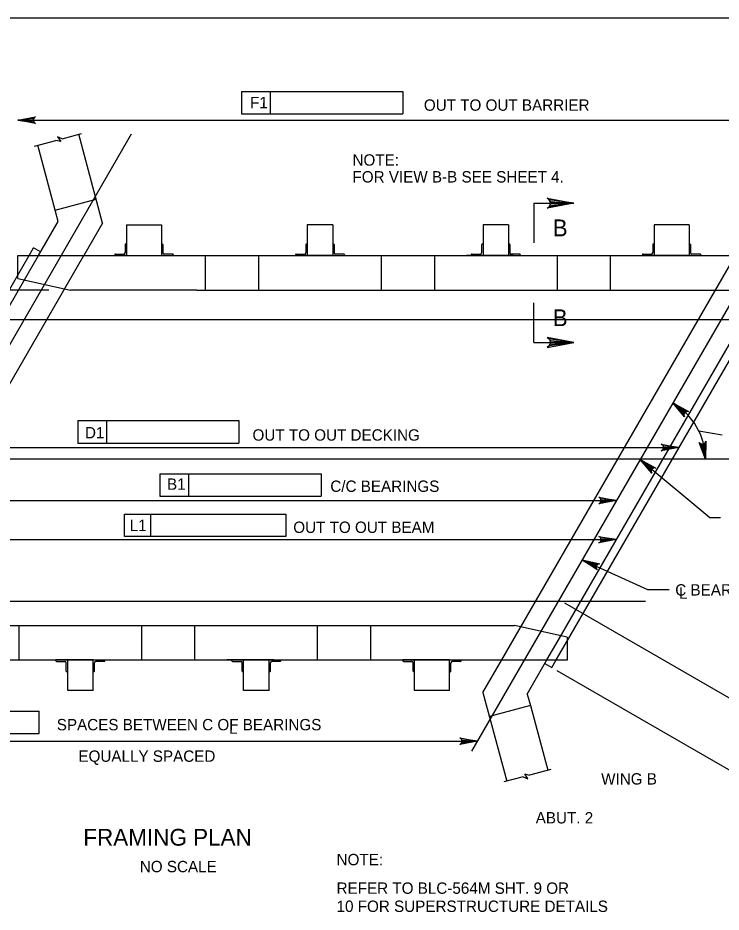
# Model space of a CAD drawing. Extents: x 638175 to 640495, y 294277 to 298435.
# Drawn here: x 638659.6 to 638845, y 295214.5 to 295450.5 of the extents above; entities that cross this region are included whole.
import ezdxf

# ---------------------------------------------------------------- set-up
doc = ezdxf.new("R2010")
doc.units = 0
for name, color, linetype in [('2', 7, 'Continuous'), ('3', 7, 'Continuous'), ('4', 7, 'Continuous')]:
    doc.layers.add(name, color=color, linetype=linetype)

msp = doc.modelspace()

# ---------------------------------------------------------------- linework, layer by layer
at = {"layer": '2'}
for p, q in [((638475.46, 295450.46), (639261.46, 295450.46)), ((638681.87, 295396.3), (638675.59, 295419.73)), ((638669.38, 295399.76), (638664.8, 295416.84)), ((638669.38, 295399.76), (638680.17, 295402.65)), ((638670.19, 295396.73), (638669.38, 295399.76)), ((638795.64, 295401.55), (638795.64, 295391.07)), ((638795.64, 295401.55), (638806.12, 295401.55)), ((638665, 295387.76), (638670.19, 295396.73)), ((638681.87, 295396.3), (638676.94, 295387.76)), ((638688.19, 295395.84), (638697.43, 295395.84)), ((638688.19, 295395.84), (638688.19, 295387.75)), ((638697.43, 295395.84), (638697.43, 295387.75)), ((638742.58, 295395.84), (638735.85, 295395.84)), ((638742.58, 295395.84), (638735.85, 295395.84)), ((638735.85, 295395.84), (638735.85, 295387.75)), ((638742.58, 295395.84), (638742.58, 295387.75)), ((638788.95, 295395.84), (638782.22, 295395.84)), ((638788.95, 295395.84), (638782.22, 295395.84)), ((638788.95, 295395.84), (638782.22, 295395.84)), ((638782.22, 295395.84), (638782.22, 295387.75)), ((638788.95, 295395.84), (638788.95, 295387.75)), ((638836.56, 295395.84), (638827.33, 295395.84)), ((638827.33, 295395.84), (638827.33, 295387.75)), ((638836.56, 295395.84), (638836.56, 295387.75)), ((638687.83, 295390.66), (638687.83, 295388.48)), ((638688.01, 295390.84), (638688.19, 295390.84)), ((638688.19, 295390.84), (638688.19, 295387.75)), ((638697.61, 295390.84), (638697.43, 295390.84)), ((638697.43, 295390.84), (638697.43, 295387.75)), ((638697.79, 295390.66), (638697.79, 295388.48)), ((638735.49, 295390.66), (638735.49, 295388.48)), ((638735.67, 295390.84), (638735.85, 295390.84)), ((638735.85, 295390.84), (638735.85, 295387.75)), ((638742.76, 295390.84), (638742.58, 295390.84)), ((638742.58, 295390.84), (638742.58, 295387.75)), ((638742.95, 295390.66), (638742.95, 295388.48)), ((638781.85, 295390.66), (638781.85, 295388.48)), ((638782.04, 295390.84), (638782.22, 295390.84)), ((638782.22, 295390.84), (638782.22, 295387.75)), ((638789.13, 295390.84), (638788.95, 295390.84)), ((638788.95, 295390.84), (638788.95, 295387.75)), ((638789.31, 295390.66), (638789.31, 295388.48)), ((638826.96, 295390.66), (638826.96, 295388.48)), ((638827.15, 295390.84), (638827.33, 295390.84)), ((638827.33, 295390.84), (638827.33, 295387.75)), ((638836.75, 295390.84), (638836.56, 295390.84)), ((638836.56, 295390.84), (638836.56, 295387.75)), ((638836.93, 295390.66), (638836.93, 295388.48)), ((638615.32, 295281.03), (638676.94, 295387.76)), ((638659.57, 295387.75), (638863.14, 295387.75)), ((638659.57, 295382.59), (638662.55, 295387.75)), ((638659.57, 295381.72), (638659.57, 295387.75)), ((638662.02, 295382.59), (638665, 295387.76)), ((638662.55, 295387.75), (638663.71, 295389.77)), ((638665.56, 295388.71), (638663.71, 295389.77)), ((638665, 295387.76), (638860.69, 295387.76)), ((638685.1, 295387.94), (638685.1, 295387.75)), ((638688.19, 295387.75), (638685.1, 295387.75)), ((638685.28, 295388.12), (638687.46, 295388.12)), ((638688.19, 295387.75), (638697.43, 295387.75)), ((638697.43, 295387.75), (638700.52, 295387.75)), ((638700.34, 295388.12), (638698.15, 295388.12)), ((638700.52, 295387.94), (638700.52, 295387.75)), ((638708.98, 295387.75), (638708.98, 295378.63)), ((638723.05, 295387.75), (638723.05, 295378.63)), ((638732.76, 295387.94), (638732.76, 295387.75)), ((638735.85, 295387.75), (638732.76, 295387.75)), ((638732.95, 295388.12), (638735.13, 295388.12)), ((638742.58, 295387.75), (638735.85, 295387.75)), ((638742.58, 295387.75), (638735.85, 295387.75)), ((638742.58, 295387.75), (638745.67, 295387.75)), ((638745.49, 295388.12), (638743.31, 295388.12)), ((638745.67, 295387.94), (638745.67, 295387.75)), ((638755.39, 295387.75), (638755.39, 295378.63)), ((638769.41, 295387.75), (638769.41, 295378.63)), ((638780.96, 295387.75), (638777.87, 295387.75)), ((638779.13, 295387.94), (638779.13, 295387.75)), ((638782.22, 295387.75), (638779.13, 295387.75)), ((638779.31, 295388.12), (638781.49, 295388.12)), ((638790.2, 295387.75), (638780.96, 295387.75)), ((638788.95, 295387.75), (638782.22, 295387.75)), ((638788.95, 295387.75), (638782.22, 295387.75)), ((638787.14, 295281.03), (638848.76, 295387.76)), ((638788.95, 295387.75), (638792.04, 295387.75)), ((638791.85, 295388.12), (638789.67, 295388.12)), ((638790.2, 295387.75), (638793.29, 295387.75)), ((638792.04, 295387.94), (638792.04, 295387.75)), ((638801.75, 295387.75), (638801.75, 295378.63)), ((638815.78, 295387.75), (638815.78, 295378.63)), ((638824.24, 295387.94), (638824.24, 295387.75)), ((638827.33, 295387.75), (638824.24, 295387.75)), ((638824.42, 295388.12), (638826.6, 295388.12)), ((638836.56, 295387.75), (638827.33, 295387.75)), ((638836.56, 295387.75), (638839.65, 295387.75)), ((638839.47, 295388.12), (638837.29, 295388.12)), ((638839.65, 295387.94), (638839.65, 295387.75)), ((638604.93, 295287.95), (638659.57, 295382.59)), ((638606.97, 295287.25), (638662.02, 295382.59)), ((638659.57, 295381.72), (638673.41, 295378.63)), ((638802.05, 295286.2), (638857.1, 295381.54)), ((638804.51, 295286.2), (638859.56, 295381.54)), ((638706.72, 295378.63), (638673.41, 295378.63)), ((638706.72, 295378.63), (638849.29, 295378.63)), ((638795.64, 295364.82), (638795.64, 295375.31)), ((638795.64, 295364.82), (638806.12, 295364.82)), ((638648.08, 295290.15), (638790.52, 295290.15)), ((638659.88, 295281.03), (638659.88, 295290.15)), ((638692.22, 295281.03), (638692.22, 295290.15)), ((638706.24, 295281.03), (638706.24, 295290.15)), ((638738.58, 295281.03), (638738.58, 295290.15)), ((638752.61, 295281.03), (638752.61, 295290.15)), ((638804.39, 295287.05), (638790.52, 295290.15)), ((638799.07, 295281.03), (638802.05, 295286.2)), ((638801.53, 295281.03), (638804.51, 295286.2)), ((638804.39, 295287.05), (638804.39, 295281.03)), ((638600.93, 295281.03), (638804.51, 295281.03)), ((638600.93, 295281.03), (638799.6, 295281.03)), ((638603.38, 295281.03), (638802.05, 295281.03)), ((638669.59, 295280.84), (638669.59, 295281.03)), ((638672.69, 295281.03), (638669.59, 295281.03)), ((638669.78, 295280.66), (638671.96, 295280.66)), ((638672.32, 295278.12), (638672.32, 295280.3)), ((638679.41, 295281.03), (638672.69, 295281.03)), ((638679.41, 295281.03), (638672.69, 295281.03)), ((638672.69, 295277.94), (638672.69, 295281.03)), ((638672.69, 295272.94), (638672.69, 295281.03)), ((638679.41, 295281.03), (638682.5, 295281.03)), ((638679.41, 295277.94), (638679.41, 295281.03)), ((638679.41, 295272.94), (638679.41, 295281.03)), ((638679.78, 295278.12), (638679.78, 295280.3)), ((638682.32, 295280.66), (638680.14, 295280.66)), ((638682.5, 295280.84), (638682.5, 295281.03)), ((638717.79, 295281.03), (638714.7, 295281.03)), ((638715.96, 295280.84), (638715.96, 295281.03)), ((638719.05, 295281.03), (638715.96, 295281.03)), ((638716.14, 295280.66), (638718.32, 295280.66)), ((638727.03, 295281.03), (638717.79, 295281.03)), ((638718.69, 295278.12), (638718.69, 295280.3)), ((638725.78, 295281.03), (638719.05, 295281.03)), ((638725.78, 295281.03), (638719.05, 295281.03)), ((638719.05, 295277.94), (638719.05, 295281.03)), ((638719.05, 295272.94), (638719.05, 295281.03)), ((638725.78, 295281.03), (638728.87, 295281.03)), ((638725.78, 295277.94), (638725.78, 295281.03)), ((638725.78, 295272.94), (638725.78, 295281.03)), ((638726.14, 295278.12), (638726.14, 295280.3)), ((638728.69, 295280.66), (638726.5, 295280.66)), ((638727.03, 295281.03), (638730.12, 295281.03)), ((638728.87, 295280.84), (638728.87, 295281.03)), ((638761.07, 295280.84), (638761.07, 295281.03)), ((638764.16, 295281.03), (638761.07, 295281.03)), ((638761.25, 295280.66), (638763.43, 295280.66)), ((638763.79, 295278.12), (638763.79, 295280.3)), ((638773.39, 295281.03), (638764.16, 295281.03)), ((638764.16, 295272.94), (638764.16, 295281.03)), ((638764.16, 295277.94), (638764.16, 295281.03)), ((638773.39, 295281.03), (638776.49, 295281.03)), ((638773.39, 295272.94), (638773.39, 295281.03)), ((638773.39, 295277.94), (638773.39, 295281.03)), ((638773.76, 295278.12), (638773.76, 295280.3)), ((638776.3, 295280.66), (638774.12, 295280.66)), ((638776.49, 295280.84), (638776.49, 295281.03)), ((638782.2, 295272.48), (638787.14, 295281.03)), ((638793.89, 295272.05), (638799.07, 295281.03)), ((638798.52, 295280.07), (638800.36, 295279.01)), ((638800.36, 295279.01), (638801.53, 295281.03)), ((638672.5, 295277.94), (638672.69, 295277.94)), ((638679.59, 295277.94), (638679.41, 295277.94)), ((638718.87, 295277.94), (638719.05, 295277.94)), ((638725.96, 295277.94), (638725.78, 295277.94)), ((638763.98, 295277.94), (638764.16, 295277.94)), ((638773.58, 295277.94), (638773.39, 295277.94)), ((638679.41, 295272.94), (638672.69, 295272.94)), ((638679.41, 295272.94), (638672.69, 295272.94)), ((638725.78, 295272.94), (638719.05, 295272.94)), ((638725.78, 295272.94), (638719.05, 295272.94)), ((638725.78, 295272.94), (638719.05, 295272.94)), ((638773.39, 295272.94), (638764.16, 295272.94)), ((638782.2, 295272.48), (638788.48, 295249.06)), ((638793.89, 295272.05), (638794.7, 295269.03)), ((638638.68, 295267.51), (638665.18, 295267.51)), ((638665.18, 295261.6), (638665.18, 295267.51)), ((638794.7, 295269.03), (638783.91, 295266.13)), ((638794.7, 295269.03), (638799.27, 295251.95)), ((638638.67, 295261.6), (638665.18, 295261.6))]:
    msp.add_line(p, q, dxfattribs=at)
for points in [[(638806.12, 295401.55), (638799.13, 295400.24), (638799.67, 295400.62), (638799.95, 295401.08), (638800.03, 295401.55), (638799.95, 295402.02), (638799.67, 295402.49), (638799.13, 295402.86), (638806.12, 295401.55), (638799.67, 295402.49), (638799.95, 295402.02), (638806.12, 295401.55), (638800.03, 295401.55), (638799.95, 295401.08), (638806.12, 295401.55), (638799.67, 295400.62)], [(638806.12, 295364.82), (638799.13, 295366.13), (638799.67, 295365.76), (638799.95, 295365.29), (638800.03, 295364.82), (638799.95, 295364.35), (638799.67, 295363.89), (638799.13, 295363.51), (638806.12, 295364.82), (638799.67, 295363.89), (638799.95, 295364.35), (638806.12, 295364.82), (638800.03, 295364.82), (638799.95, 295365.29), (638806.12, 295364.82), (638799.67, 295365.76)]]:
    msp.add_lwpolyline(points, dxfattribs=at)
for centre, radius, start, end in [((638688.01, 295390.66), 0.182, 90, 179.9984), ((638697.61, 295390.66), 0.182, 0.0016, 90), ((638735.67, 295390.66), 0.182, 90, 179.9984), ((638742.76, 295390.66), 0.182, 0.0016, 90), ((638782.04, 295390.66), 0.182, 90, 179.9984), ((638789.13, 295390.66), 0.182, 0.0016, 90), ((638827.15, 295390.66), 0.182, 90, 179.9984), ((638836.75, 295390.66), 0.182, 0.0016, 90), ((638685.28, 295387.94), 0.182, 90, 179.9984), ((638687.46, 295388.48), 0.364, 270, 359.9984), ((638698.15, 295388.48), 0.364, 180.0016, 270), ((638700.34, 295387.94), 0.182, 0.0016, 90), ((638732.95, 295387.94), 0.182, 90, 179.9984), ((638735.13, 295388.48), 0.364, 270, 359.9984), ((638743.31, 295388.48), 0.364, 180.0016, 270), ((638745.49, 295387.94), 0.182, 0.0016, 90), ((638779.31, 295387.94), 0.182, 90, 179.9984), ((638781.49, 295388.48), 0.364, 270, 359.9984), ((638789.67, 295388.48), 0.364, 180.0016, 270), ((638791.85, 295387.94), 0.182, 0.0016, 90), ((638824.42, 295387.94), 0.182, 90, 179.9984), ((638826.6, 295388.48), 0.364, 270, 359.9984), ((638837.29, 295388.48), 0.364, 180.0016, 270), ((638839.47, 295387.94), 0.182, 0.0016, 90), ((638669.78, 295280.84), 0.182, 180.0016, 270), ((638671.96, 295280.3), 0.364, 0.0016, 90), ((638680.14, 295280.3), 0.364, 90, 179.9984), ((638682.32, 295280.84), 0.182, 270, 359.9984), ((638716.14, 295280.84), 0.182, 180.0016, 270), ((638718.32, 295280.3), 0.364, 0.0016, 90), ((638726.5, 295280.3), 0.364, 90, 179.9984), ((638728.69, 295280.84), 0.182, 270, 359.9984), ((638761.25, 295280.84), 0.182, 180.0016, 270), ((638763.43, 295280.3), 0.364, 0.0016, 90), ((638774.12, 295280.3), 0.364, 90, 179.9984), ((638776.3, 295280.84), 0.182, 270, 359.9984), ((638672.5, 295278.12), 0.182, 180.0016, 270), ((638679.59, 295278.12), 0.182, 270, 359.9984), ((638718.87, 295278.12), 0.182, 180.0016, 270), ((638725.96, 295278.12), 0.182, 270, 359.9984), ((638763.98, 295278.12), 0.182, 180.0016, 270), ((638773.58, 295278.12), 0.182, 270, 359.9984)]:
    msp.add_arc(centre, radius, start, end, dxfattribs=at)
at = {"layer": '3'}
for p, q in [((638671.23, 295418.56), (638670.03, 295419.08)), ((638670.03, 295419.08), (638670.85, 295417.83)), ((638671.23, 295418.56), (638676.36, 295419.93)), ((638663.96, 295416.61), (638669.56, 295418.11)), ((638670.85, 295417.83), (638669.56, 295418.11)), ((638793.22, 295250.96), (638794.51, 295250.67)), ((638794.05, 295249.71), (638793.22, 295250.96)), ((638800.11, 295252.17), (638794.51, 295250.67)), ((638792.84, 295250.22), (638787.72, 295248.85)), ((638792.84, 295250.22), (638794.05, 295249.71))]:
    msp.add_line(p, q, dxfattribs=at)
at = {"layer": '4'}
for p, q in [((638718.57, 295431.06), (638761.09, 295431.06)), ((638718.57, 295431.06), (638718.57, 295425.15)), ((638726.13, 295431.06), (638726.13, 295425.15)), ((638761.09, 295431.06), (638761.09, 295425.15)), ((638659.57, 295423.47), (638863.14, 295423.47)), ((638718.57, 295425.15), (638761.09, 295425.15)), ((638689.46, 295419.78), (638595.44, 295256.93)), ((638873.21, 295419.78), (638779.19, 295256.93)), ((638667.7, 295378.63), (638501.09, 295378.63)), ((638863.78, 295370.8), (638515.73, 295370.8)), ((638675.34, 295344.19), (638717.86, 295344.19)), ((638675.34, 295344.19), (638675.34, 295338.28)), ((638682.9, 295344.19), (638682.9, 295338.28)), ((638717.86, 295344.19), (638717.86, 295338.28)), ((638839.13, 295341.47), (638845.27, 295340.44)), ((638675.34, 295338.28), (638717.86, 295338.28)), ((638633.3, 295337.09), (638833.89, 295337.09)), ((638882.76, 295333.98), (638590.47, 295333.98)), ((638823.67, 295333.97), (638842.03, 295318.63)), ((638696.99, 295330.16), (638739.51, 295330.16)), ((638696.99, 295330.16), (638696.99, 295324.26)), ((638704.55, 295330.16), (638704.55, 295324.26)), ((638739.51, 295330.16), (638739.51, 295324.26)), ((638696.99, 295324.26), (638739.51, 295324.26)), ((638633.64, 295323.11), (638817.4, 295323.11)), ((638687.7, 295319.52), (638730.22, 295319.52)), ((638687.7, 295313.61), (638687.7, 295319.52)), ((638694.59, 295313.61), (638694.59, 295319.52)), ((638730.22, 295319.52), (638730.22, 295313.61)), ((638842.03, 295318.63), (638844.87, 295318.63)), ((638621.72, 295312.78), (638817.4, 295312.78)), ((638730.22, 295313.61), (638687.7, 295313.61)), ((638808.38, 295307.49), (638825.58, 295299.6)), ((638825.58, 295299.6), (638831.33, 295299.6)), ((638825.02, 295296.45), (638515.26, 295296.45)), ((638803.69, 295296.11), (638881.52, 295251.18)), ((638801.71, 295278.23), (638908.35, 295216.66)), ((638596.97, 295259.58), (638780.72, 295259.58)), ((638600.15, 295259.58), (638777.9, 295259.58))]:
    msp.add_line(p, q, dxfattribs=at)
for points in [[(638659.57, 295423.47), (638664.23, 295424.35), (638663.87, 295424.1), (638663.68, 295423.79), (638663.63, 295423.47), (638663.68, 295423.16), (638663.87, 295422.85), (638664.23, 295422.6), (638659.57, 295423.47), (638663.87, 295422.85), (638663.68, 295423.16), (638659.57, 295423.47), (638663.63, 295423.47), (638663.68, 295423.79), (638659.57, 295423.47), (638663.87, 295424.1)], [(638832.27, 295348.85), (638836.43, 295346.57), (638835.99, 295346.6), (638835.65, 295346.48), (638835.41, 295346.27), (638835.26, 295346), (638835.2, 295345.64), (638835.32, 295345.22), (638832.27, 295348.85), (638835.2, 295345.64), (638835.26, 295346), (638832.27, 295348.85), (638835.41, 295346.27), (638835.65, 295346.48), (638832.27, 295348.85), (638835.99, 295346.6)], [(638840.85, 295333.99), (638839.25, 295338.45), (638839.55, 295338.14), (638839.89, 295338), (638840.21, 295338), (638840.51, 295338.1), (638840.79, 295338.33), (638840.98, 295338.73), (638840.85, 295333.99), (638840.79, 295338.33), (638840.51, 295338.1), (638840.85, 295333.99), (638840.21, 295338), (638839.89, 295338), (638840.85, 295333.99), (638839.55, 295338.14)], [(638833.89, 295337.09), (638829.23, 295336.21), (638829.59, 295336.46), (638829.78, 295336.77), (638829.83, 295337.09), (638829.78, 295337.4), (638829.59, 295337.71), (638829.23, 295337.96), (638833.89, 295337.09), (638829.59, 295337.71), (638829.78, 295337.4), (638833.89, 295337.09), (638829.83, 295337.09), (638829.78, 295336.77), (638833.89, 295337.09), (638829.59, 295336.46)], [(638823.67, 295333.97), (638827.81, 295331.66), (638827.37, 295331.7), (638827.03, 295331.57), (638826.79, 295331.37), (638826.63, 295331.1), (638826.57, 295330.74), (638826.69, 295330.32), (638823.67, 295333.97), (638826.57, 295330.74), (638826.63, 295331.1), (638823.67, 295333.97), (638826.79, 295331.37), (638827.03, 295331.57), (638823.67, 295333.97), (638827.37, 295331.7)], [(638817.4, 295323.11), (638812.74, 295322.23), (638813.09, 295322.48), (638813.28, 295322.79), (638813.33, 295323.11), (638813.28, 295323.42), (638813.09, 295323.73), (638812.74, 295323.98), (638817.4, 295323.11), (638813.09, 295323.73), (638813.28, 295323.42), (638817.4, 295323.11), (638813.33, 295323.11), (638813.28, 295322.79), (638817.4, 295323.11), (638813.09, 295322.48)], [(638817.4, 295312.78), (638812.74, 295311.91), (638813.1, 295312.15), (638813.28, 295312.47), (638813.34, 295312.78), (638813.28, 295313.09), (638813.1, 295313.4), (638812.74, 295313.65), (638817.4, 295312.78), (638813.1, 295313.4), (638813.28, 295313.09), (638817.4, 295312.78), (638813.34, 295312.78), (638813.28, 295312.47), (638817.4, 295312.78), (638813.1, 295312.15)], [(638808.38, 295307.49), (638812.99, 295306.37), (638812.56, 295306.29), (638812.26, 295306.08), (638812.08, 295305.82), (638812.01, 295305.51), (638812.05, 295305.16), (638812.27, 295304.78), (638808.38, 295307.49), (638812.05, 295305.16), (638812.01, 295305.51), (638808.38, 295307.49), (638812.08, 295305.82), (638812.26, 295306.08), (638808.38, 295307.49), (638812.56, 295306.29)], [(638780.72, 295259.58), (638776.06, 295258.71), (638776.42, 295258.96), (638776.61, 295259.27), (638776.66, 295259.58), (638776.61, 295259.9), (638776.42, 295260.21), (638776.06, 295260.46), (638780.72, 295259.58), (638776.42, 295260.21), (638776.61, 295259.9), (638780.72, 295259.58), (638776.66, 295259.58), (638776.61, 295259.27), (638780.72, 295259.58), (638776.42, 295258.96)]]:
    msp.add_lwpolyline(points, dxfattribs=at)
msp.add_arc((638823.67, 295333.98), 17.18, 0.0029, 59.9982, dxfattribs=at)

# ---------------------------------------------------------------- texts
at = {"layer": '2'}
for s, p in [('SPACES BETWEEN C OF BEARINGS', (638669.82, 295262.47)), ('L', (638715.26, 295261.56)), ('EQUALLY SPACED', (638675.52, 295254.16))]:
    msp.add_text(s, height=3, dxfattribs=at).set_placement(p)
at = {"layer": '4'}
for s, height, rotation, p in [('F1', 3, 359.9382, (638720.78, 295426.61)), ('B', 4.43, 360, (638800.58, 295392.83)), ('D1', 3, 359.9382, (638677.25, 295339.51)), ('B1', 3, 359.9382, (638698.89, 295325.94))]:
    msp.add_text(s, height=height, rotation=rotation, dxfattribs=at).set_placement(p)
for s, height, p in [('OUT TO OUT BARRIER ', 3, (638766.62, 295425.95)), ('NOTE:', 3, (638747.79, 295411.46)), ('FOR VIEW B-B SEE SHEET 4.', 3, (638747.79, 295407.02)), ('B', 4.43, (638800.58, 295369.12)), ('OUT TO OUT DECKING', 3, (638721.43, 295338.9)), ('C/C BEARINGS', 3, (638741.95, 295325.38)), ('L1', 3, (638689.02, 295315.04)), ('OUT TO OUT BEAM', 3, (638732.18, 295314.55)), ('C BEARINGS', 3, (638832.91, 295298.03)), ('L', 3, (638833.9, 295297.18)), ('WING B', 3, (638813.37, 295248.16)), ('ABUT. 2', 3, (638796.11, 295237.9)), ('FRAMING PLAN', 4.4292, (638676.81, 295232.04)), ('NOTE:', 3, (638743.6, 295226.87)), ('NO SCALE', 3, (638691.71, 295225.03)), ('REFER TO BLC-564M SHT. 9 OR', 3, (638743.6, 295219.33)), ('10 FOR SUPERSTRUCTURE DETAILS', 3, (638743.6, 295214.55))]:
    msp.add_text(s, height=height, dxfattribs=at).set_placement(p)

doc.saveas('drawing.dxf')
